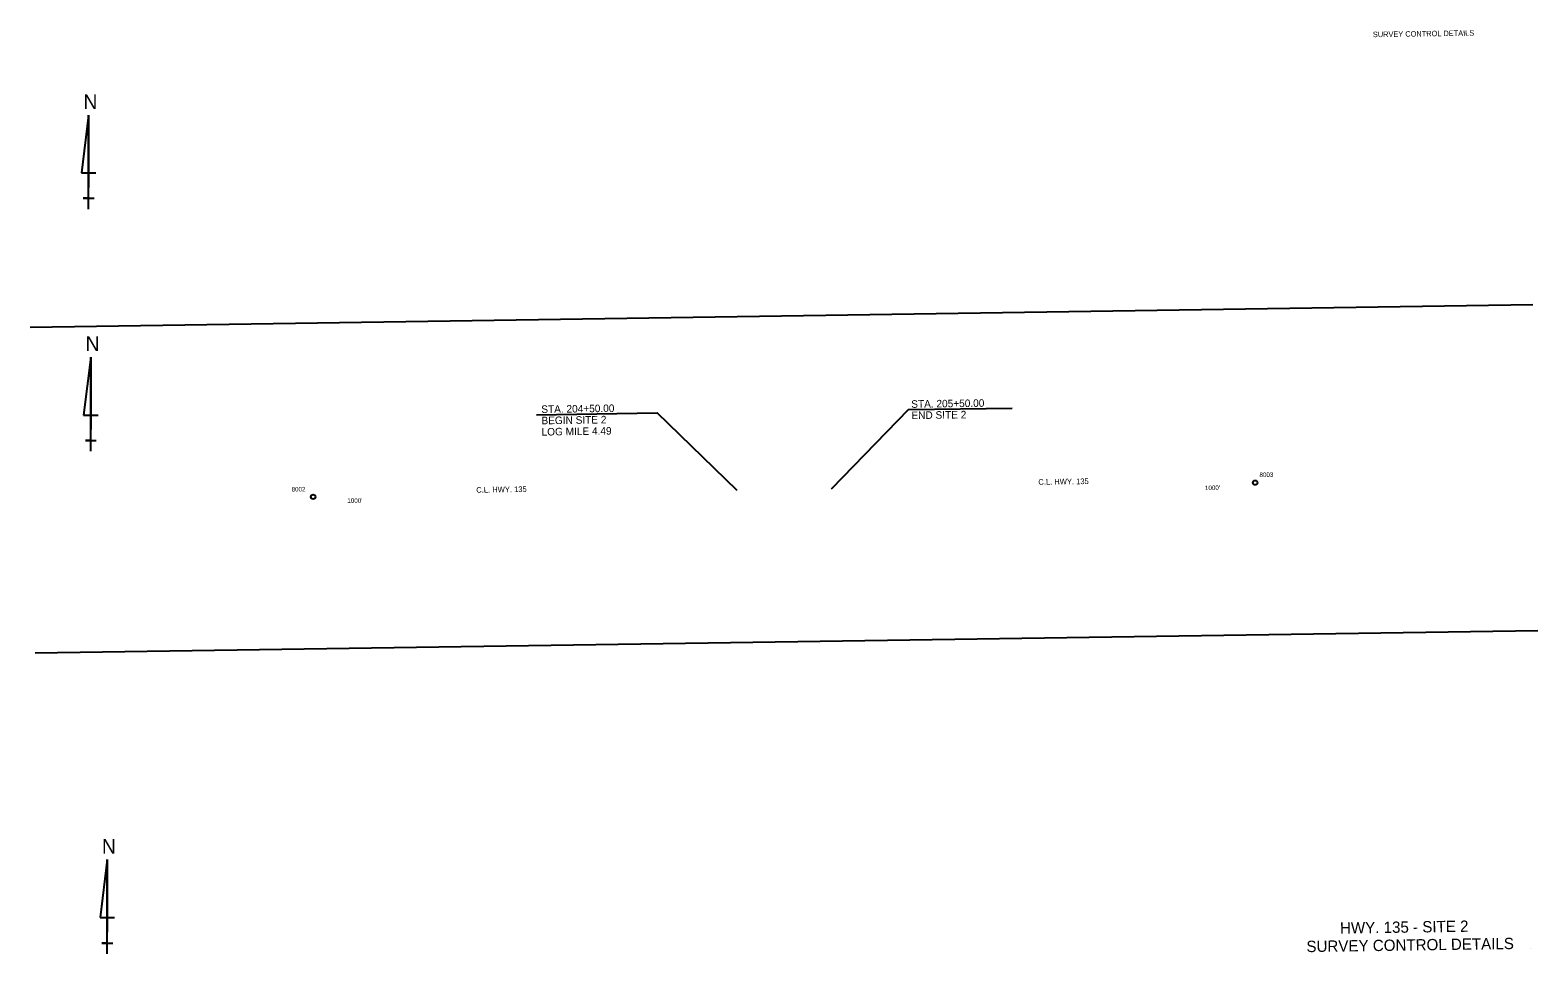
# Model space of a CAD drawing. Extents: x 1799865 to 1801466, y 522121 to 523102.
import ezdxf

# ---------------------------------------------------------------- set-up
doc = ezdxf.new("R2010")
doc.units = 0
for name, color, linetype in [('S_BASELINE', 7, 'Continuous'), ('S_SANITARY_SEWER', 7, 'Continuous'), ('S_SIDE_DRAIN', 7, 'Continuous')]:
    doc.layers.add(name, color=color, linetype=linetype)

msp = doc.modelspace()

# ---------------------------------------------------------------- linework, layer by layer
at = {"layer": 'S_BASELINE'}
for p, q in [((1799927.5, 523011.7), (1799919.9, 522950.2)), ((1799927.5, 522911.7), (1799927.5, 523011.7)), ((1799927.5, 523011.7), (1799927.5, 522934.8)), ((1799919.9, 522950.2), (1799935.2, 522950.2)), ((1799927.5, 522911.7), (1799927.5, 522934.8)), ((1799927.5, 522923.3), (1799921.8, 522923.3)), ((1799921.8, 522923.3), (1799933.3, 522923.3)), ((1799927.5, 522911.7), (1799927.5, 522923.3)), ((1799929.8, 522754.7), (1799922.1, 522693.2)), ((1799929.8, 522654.7), (1799929.8, 522754.7)), ((1799929.8, 522754.7), (1799929.8, 522677.8)), ((1799922.1, 522693.2), (1799937.5, 522693.2)), ((1800402.9, 522693.5), (1800530.9, 522695.4)), ((1800615.8, 522613), (1800530.9, 522695.4)), ((1800797.8, 522699), (1800715.7, 522614.5)), ((1800797.8, 522699), (1800907.7, 522700.6)), ((1799929.8, 522654.7), (1799929.8, 522677.8)), ((1799929.8, 522666.3), (1799924, 522666.3)), ((1799924, 522666.3), (1799935.6, 522666.3)), ((1799929.8, 522654.7), (1799929.8, 522666.3)), ((1799947.3, 522221.1), (1799939.6, 522159.6)), ((1799947.3, 522121.1), (1799947.3, 522221.1)), ((1799947.3, 522221.1), (1799947.3, 522144.2)), ((1799939.6, 522159.6), (1799955, 522159.6)), ((1799947.3, 522132.6), (1799941.5, 522132.6)), ((1799941.5, 522132.6), (1799953, 522132.6)), ((1799947.3, 522121.1), (1799947.3, 522144.2)), ((1799947.3, 522121.1), (1799947.3, 522132.6))]:
    msp.add_line(p, q, dxfattribs=at)
at = {"layer": 'S_SANITARY_SEWER'}
for centre in [(1801165.7, 522621.3), (1800165.8, 522606.3)]:
    msp.add_circle(centre, 2.38, dxfattribs=at)
at = {"layer": 'S_SIDE_DRAIN'}
for p, q in [((1799865.4, 522786.6), (1801460.6, 522810.4)), ((1799870.6, 522440.6), (1801465.8, 522464.5)), ((1801458.3, 522126.5), (1801458.3, 522126.5))]:
    msp.add_line(p, q, dxfattribs=at)

# ---------------------------------------------------------------- texts
at = {"layer": 'S_BASELINE'}
for s, height, rotation, p in [('N', 15.4, 360, (1799921.9, 523018.2)), ('N', 15.4, 360, (1799924.2, 522761.2)), ('STA. 205+50.00', 8, 0.8565, (1800800.7, 522700.8)), ('STA. 204+50.00', 8, 0.8565, (1800408, 522695.3)), ('BEGIN SITE 2', 8, 0.8565, (1800408.2, 522683.3)), ('END SITE 2', 8, 0.8565, (1800800.9, 522688.8)), ('LOG MILE 4.49', 8, 0.8565, (1800408.3, 522671.3)), ('8003', 4.8, 0.8565, (1801170.3, 522627.3)), ('8002', 4.8, 0.8565, (1800143, 522611.9)), ('C.L. HWY. 135', 6, 0.8565, (1800339, 522610.7)), ('C.L. HWY. 135', 6, 0.8565, (1800935.6, 522619.1)), ("1000'", 4.8, 0.8565, (1801112.4, 522613.4)), ("1000'", 4.8, 0.8565, (1800202.1, 522599.8)), ('N', 15.4, 360, (1799941.6, 522227.5)), ('HWY. 135 - SITE 2', 12, 0.8565, (1801255.8, 522142.5)), ('SURVEY CONTROL DETAILS', 12, 0.8565, (1801220.2, 522122.9))]:
    msp.add_text(s, height=height, rotation=rotation, dxfattribs=at).set_placement(p)
at = {"layer": 'S_SIDE_DRAIN'}
msp.add_text('SURVEY CONTROL DETAILS', height=5.862, rotation=0.8565, dxfattribs=at).set_placement((1801290.7, 523094.3))

doc.saveas('drawing.dxf')
